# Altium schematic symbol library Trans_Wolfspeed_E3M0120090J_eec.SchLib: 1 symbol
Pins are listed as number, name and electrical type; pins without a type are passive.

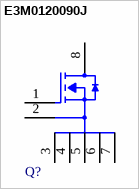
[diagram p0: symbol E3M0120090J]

## E3M0120090J
designator Q?  (value not drawn)
pins: 1 Gate, 2 Driver Source, 3 Power Source, 4 Power Source, 5 Power Source, 6 Power Source, 7 Power Source, 8 Drain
